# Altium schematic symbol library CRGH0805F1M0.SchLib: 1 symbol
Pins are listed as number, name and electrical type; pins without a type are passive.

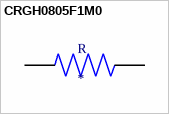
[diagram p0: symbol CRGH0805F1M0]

## CRGH0805F1M0
designator R, comment 8-1879512-5  (value not drawn)
Res Thick Film 0805 1M Ohm 1% 1/3W Â±100ppm/Â°C Molded SMD SMD T/R; MF: TE Connectivity; Voltage_Rating: 150 V; MP: CRGH0805F1M0; Power_Rating: .33 W
footprint RESC2012X65N
pins: 1, 2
